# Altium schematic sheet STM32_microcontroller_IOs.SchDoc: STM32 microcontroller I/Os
size A4; Date: Not used; ApprovedBy: Not used; CheckedBy: Not used; Author: Not used; CompanyName: STMicroelectronics; DrawnBy: Not used; Engineer: Not used; Organization: Not used; Address1: Not used; Address2: Not used; Address3: Not used; Address4: Not used; DocumentNumber: 3; Revision: Not used; SheetNumber: 3; SheetTotal: 8
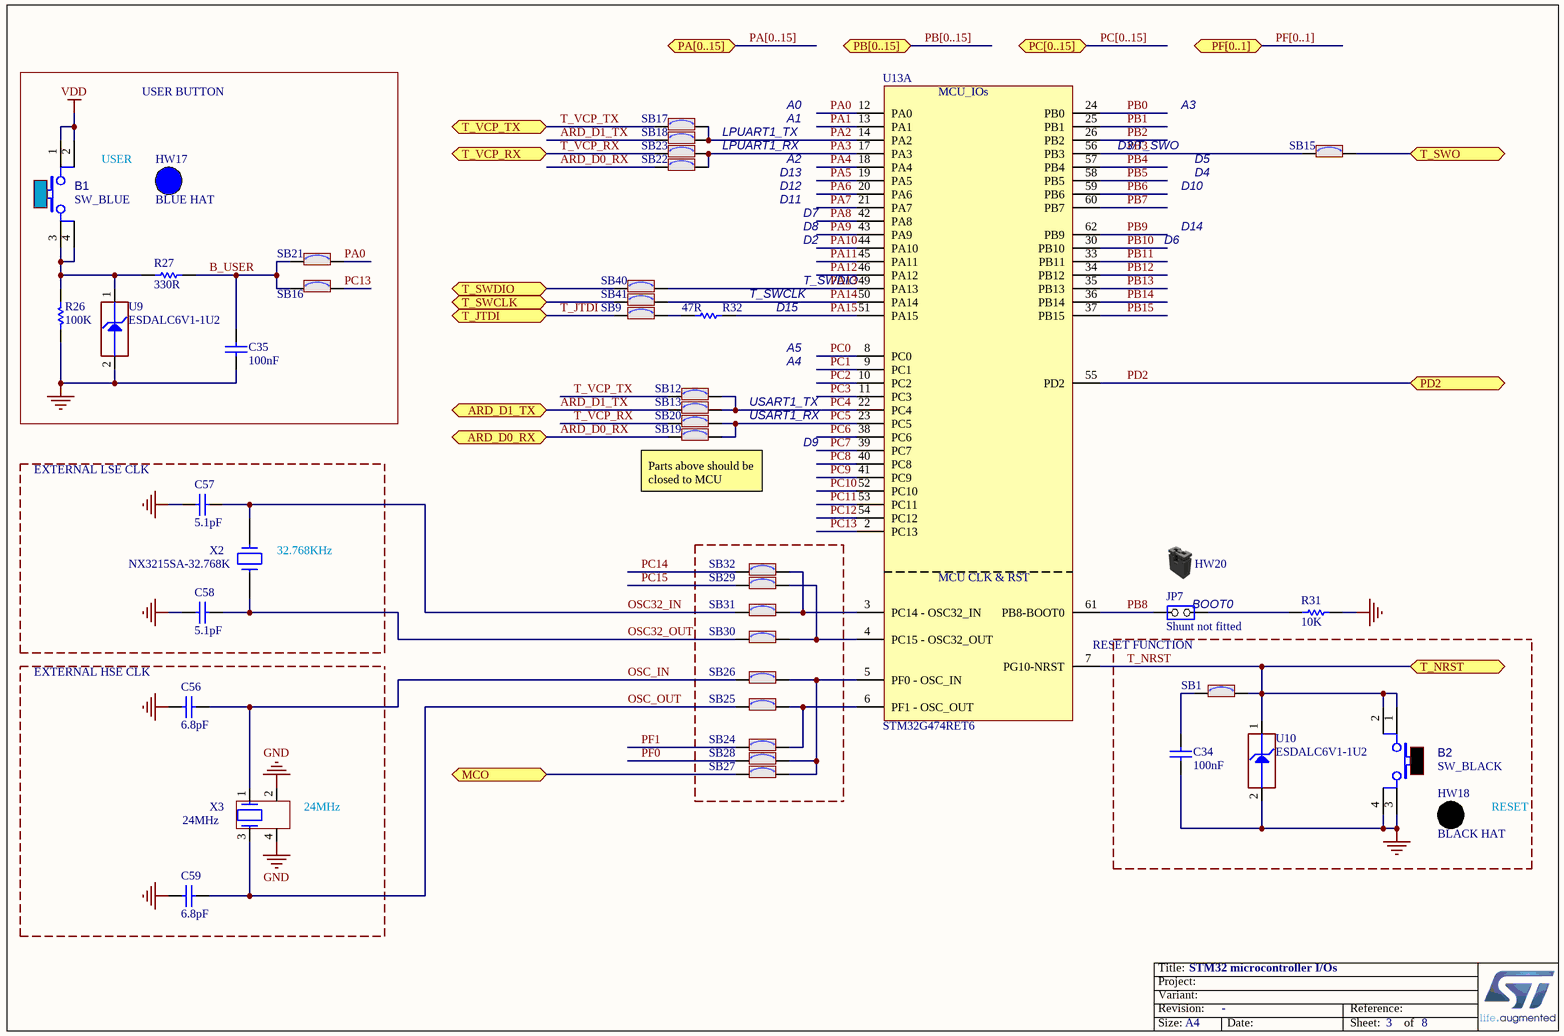
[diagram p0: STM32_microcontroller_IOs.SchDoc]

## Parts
B1  value SW_BLUE  [SWI_WEALTHMETAL_TD-0341_4P_BLUE]
B2  value SW_BLACK  [SWI_WEALTHMETAL_TD-0341_4P_BLACK]
C34  value 100nF  [C0402]
C35  value 100nF  [C0402]
C56  value 6.8pF  [C0402]
C57  value 5.1pF  [C0402]
C58  value 5.1pF  [C0402]
C59  value 6.8pF  [C0402]
HW17  value BLUE HAT  (mechanical)
HW18  value BLACK HAT  (mechanical)
HW20  (no value)  (mechanical)
JP7  value Shunt not fitted  [CON_SAMTEC_TSW-102-07-G-S]
R26  value 100K  [R0603]
R27  value 330R  [R0603]
R31  value 10K  [R0603]
R32  value 47R  [R0402]  (hidden comment: Resistor)
SB1  (no value)  [SOLDER-BRIDGE_R0603-0R]
SB9  (no value)  [SOLDER-BRIDGE_R0603-0R]
SB12  (no value)  [SOLDER-BRIDGE_R0603-0R]
SB13  (no value)  [SOLDER-BRIDGE_R0603-0R]
SB15  (no value)  [SOLDER-BRIDGE_R0603-0R]
SB16  (no value)  [SOLDER-BRIDGE_R0603-0R]
SB17  (no value)  [SOLDER-BRIDGE_R0603-0R]
SB18  (no value)  [SOLDER-BRIDGE_R0603-0R]
SB19  (no value)  [SOLDER-BRIDGE_R0603-0R]
SB20  (no value)  [SOLDER-BRIDGE_R0603-0R]
SB21  (no value)  [SOLDER-BRIDGE_R0603-0R]
SB22  (no value)  [SOLDER-BRIDGE_R0603-0R]
SB23  (no value)  [SOLDER-BRIDGE_R0603-0R]
SB24  (no value)  [SOLDER-BRIDGE_R0603-0R]
SB25  (no value)  [SOLDER-BRIDGE_R0603-0R]
SB26  (no value)  [SOLDER-BRIDGE_R0603-0R]
SB27  (no value)  [SOLDER-BRIDGE_R0603-0R]
SB28  (no value)  [SOLDER-BRIDGE_R0603-0R]
SB29  (no value)  [SOLDER-BRIDGE_R0603-0R]
SB30  (no value)  [SOLDER-BRIDGE_R0603-0R]
SB31  (no value)  [SOLDER-BRIDGE_R0603-0R]
SB32  (no value)  [SOLDER-BRIDGE_R0603-0R]
SB40  (no value)  [SOLDER-BRIDGE_R0603-0R]
SB41  (no value)  [SOLDER-BRIDGE_R0603-0R]
U9  value ESDALC6V1-1U2  [ESD_ST0201]
U10  value ESDALC6V1-1U2  [ESD_ST0201]
U13  value STM32G474RET6  [ICC_LQFP64_10X10_P050_SOCKET_YAMAICHI_IC149-064-069-B5_NM]  (hidden comment: STM32G4xx_LQFP64)  (part A of 2)
X2  value NX3215SA-32.768K  [CRY_NX3215SA_2P]
X3  value 24MHz  [CRY_NX2016SA_4P]

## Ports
ARD_D0_RX, ARD_D1_TX, MCO, PA[0..15] (bidir), PB[0..15] (bidir), PC[0..15] (bidir), PD2, PF[0..1] (bidir), T_JTDI, T_NRST, T_SWCLK, T_SWDIO, T_SWO, T_VCP_RX, T_VCP_TX

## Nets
GND: B2.3 B2.4 C34.1 C35.1 C56.1 C57.2 C58.2 C59.1 R26.1 R31.1 U9.2(GND) U10.2(GND) X3.2 X3.4
VDD: B1.1 B1.2
ARD_D0_RX: SB19.2 SB22.2 ; port ARD_D0_RX
ARD_D1_TX: SB13.2 SB18.2 ; port ARD_D1_TX
B_USER: C35.2 R27.2 SB16.1 SB21.1
MCO: SB27.1 ; port MCO
OSC32_IN: C57.1 SB31.1 X2.1
OSC32_OUT: C58.1 SB30.1 X2.2
OSC_IN: C56.2 SB26.1 X3.1
OSC_OUT: C59.2 SB25.1 X3.3
PA0: SB21.2 U13.12(PA0)
PA1: U13.13(PA1)
PA2: SB17.2 SB18.1 U13.14(PA2)
PA3: SB22.1 SB23.2 U13.17(PA3)
PA4: U13.18(PA4)
PA5: U13.19(PA5)
PA6: U13.20(PA6)
PA7: U13.21(PA7)
PA8: U13.42(PA8)
PA9: U13.43(PA9)
PA10: U13.44(PA10)
PA11: U13.45(PA11)
PA12: U13.46(PA12)
PA13: SB40.2 U13.49(PA13)
PA14: SB41.2 U13.50(PA14)
PA15: R32.2 U13.51(PA15)
PB0: U13.24(PB0)
PB1: U13.25(PB1)
PB2: U13.26(PB2)
PB3: SB15.1 U13.56(PB3)
PB4: U13.57(PB4)
PB5: U13.58(PB5)
PB6: U13.59(PB6)
PB7: U13.60(PB7)
PB8: JP7.1(COMMON) U13.61(PB8-BOOT0)
PB9: U13.62(PB9)
PB10: U13.30(PB10)
PB11: U13.33(PB11)
PB12: U13.34(PB12)
PB13: U13.35(PB13)
PB14: U13.36(PB14)
PB15: U13.37(PB15)
PC0: U13.8(PC0)
PC1: U13.9(PC1)
PC2: U13.10(PC2)
PC3: U13.11(PC3)
PC4: SB12.2 SB13.1 U13.22(PC4)
PC5: SB19.1 SB20.2 U13.23(PC5)
PC6: U13.38(PC6)
PC7: U13.39(PC7)
PC8: U13.40(PC8)
PC9: U13.41(PC9)
PC10: U13.52(PC10)
PC11: U13.53(PC11)
PC12: U13.54(PC12)
PC13: SB16.2 U13.2(PC13)
PC14: SB32.1
PC15: SB29.1
PD2: U13.55(PD2) ; port PD2
PF0: SB28.1
PF1: SB24.1
T_JTDI: SB9.1 ; port T_JTDI
T_NRST: B2.1 B2.2 SB1.2 U10.1(IO1) U13.7(PG10-NRST) ; port T_NRST
T_SWCLK: SB41.1 ; port T_SWCLK
T_SWDIO: SB40.1 ; port T_SWDIO
T_SWO: SB15.2 ; port T_SWO
T_VCP_RX: SB20.1 SB23.1 ; port T_VCP_RX
T_VCP_TX: SB12.1 SB17.1 ; port T_VCP_TX
NetB1_3: B1.3 B1.4 R26.2 R27.1 U9.1(IO1)
NetC34_2: C34.2 SB1.1
NetJP7_2: JP7.2(NO) R31.2
NetR32_1: R32.1 SB9.2
NetSB24_2: SB24.2 SB25.2 U13.6(PF1_-_OSC_OUT)
NetSB26_2: SB26.2 SB27.2 SB28.2 U13.5(PF0_-_OSC_IN)
NetSB29_2: SB29.2 SB30.2 U13.4(PC15_-_OSC32_OUT)
NetSB31_2: SB31.2 SB32.2 U13.3(PC14_-_OSC32_IN)

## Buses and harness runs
bus PA[0..15] = port PA[0..15]
bus PB[0..15] = port PB[0..15]
bus PC[0..15] = port PC[0..15]
bus PF[0..1] = port PF[0..1]

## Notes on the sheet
- USER BUTTON
- A0
- A3
- USER
- LPUART1_TX
- LPUART1_RX
- A1
- A2
- D13
- D3/T_SWO
- D4
- D5
- D12
- D11
- D2
- D7
- D8
- D14
- D10
- D6
- (near R32) T_SWCLK
- D15
- (near R32) T_SWDIO
- A4
- A5
- USART1_RX
- USART1_TX
- D9
- EXTERNAL LSE CLK
- (near SB19) Parts above should be closed to MCU
- (near X2) 32.768KHz
- RESET FUNCTION
- BOOT0
- EXTERNAL HSE CLK
- (near X3) 24MHz
- RESET

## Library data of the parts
B1 = MCD-00002: Non-Open Push-Button 0.1A 24V; Manufacturer_Part_Number: TD0341X-G01-BLU; Manufacturer: WEALTHMETAL; Part_Type: Misc; Provided_By: Subcon; Initial_Board_Reference: MB1274
B2 = MCD-00001: Non-Open Push-Button 0.1A 24V; Manufacturer_Part_Number: TD0341X-G01-BLA; Manufacturer: WEALTHMETAL; Part_Type: Misc; Provided_By: Subcon; Initial_Board_Reference: MB1274
C34 C35 = MCD-00102: Capacitor, MLCC, 100nF, 16V, X7R, 10%, 0402, T=0,5mm; Manufacturer_Part_Number: CC0402KRX7R7BB104; Manufacturer: YAGEO; Provided_By: Subcon; Initial_Board_Reference: MB1262
C56 C59 = MCD-00674: Capacitor, MLCC, 6.8pF, 50V, NPO, +-0.25pF, 0402, T=0.5mm; Manufacturer_Part_Number: CC0402CRNPO9BN6R8; Manufacturer: YAGEO; Provided_By: Subcon; Initial_Board_Reference: MB1319
C57 C58 = MCD-00003: Capacitor, MLCC, 5.1pF, 50V, NPO, +-0.25pF, 0402, T=0.5mm; Manufacturer_Part_Number: CC0402CRNPO9BN5R1; Manufacturer: YAGEO; Provided_By: Subcon; Initial_Board_Reference: MB1274
HW17 = MCD-00634: Blue Hat for switch TD0341X-G01-BLU; Part_Type: Mechanical; Manufacturer_Part_Number: 988.16.09.3.00002_SH-517; Manufacturer: JIUBABA; Provided_By: Subcon; Initial_Board_Reference: MB1319
HW18 = MCD-00635: Black Hat for switch TD0341X-G01-BLA; Part_Type: Mechanical; Manufacturer_Part_Number: 988.16.09.3.00003_SH-517; Manufacturer: JIUBABA; Provided_By: Subcon; Initial_Board_Reference: MB1319
HW20 = MCD-00043: SHUNT 2.54mm BLACK; Manufacturer_Part_Number: SNT-100-BK-G; Manufacturer: SAMTEC; Part_Type: Mechanical; Provided_By: Subcon; Initial_Board_Reference: MB1274
JP7 = MCD-00045: Header, 2x1, 2,54mm, VR, TH, Height 5.84mm/2.54mm; Part_Type: Connector; Manufacturer_Part_Number: TSW-102-07-x-S; Manufacturer: SAMTEC; Provided_By: Subcon; Initial_Board_Reference: MB1274
R26 = MCD-00223: Resistor,100K,0603,1%,1/10W; Manufacturer_Part_Number: RC0603FR-07100KL; Manufacturer: YAGEO; Provided_By: Subcon; Initial_Board_Reference: MB1319
R27 = MCD-00197: Resistor,330R,0603,1%,1/10W; Manufacturer_Part_Number: RC0603FR-07330RL; Manufacturer: YAGEO; Provided_By: Subcon
R31 = MCD-00220: Resistor,10K,0603,1%,1/10W; Manufacturer_Part_Number: RC0603FR-0710KL; Manufacturer: YAGEO; Provided_By: Subcon; Initial_Board_Reference: MB1319
R32 = MCD-00481: Resistor,47R,0402,1%,1/16W; Manufacturer_Part_Number: RC0402FR-0747RL; Manufacturer: YAGEO; Provided_By: SUBCO
SB1 SB9 SB12 SB13 SB15-SB32 SB40 SB41 = MCD-00071: Solder Bridge ON; Part_Type: Mechanical; Provided_By: Subcon; Initial_Board_Reference: MB1274
U9 U10 = MCD-00170: ESD protection 6V1; Part_Type: Diode; Manufacturer: STMICROELECTRONICS; ECCN_US: EAR99; ECCN_EU: NEC; Provided_By: Subcon; Initial_Board_Reference: MB1274
U13 = MCD-01243: STM32G474, LQFP64 package,  3D IC footprint with 2D socket footprint.; Manufacturer: STMICROELECTRONICS; Provided_By: SUBCO with ST control; Initial_Board_Reference: MB1367; Item Type: Item; Path: ws/MCD_ApplicationBoards/Lists/MCDPARTSdatabase
X2 = MCD-00091: Crystal 32.768kHz, 6pF, -+20PPM, R=50K, SMD; Manufacturer_Part_Number: NX3215SA 32.768KHz EXS00A-MU00525; Manufacturer: NDK; Part_Type: Crystal_Osc; ECCN_US: EAR99; ECCN_EU: NEC; Provided_By: STM; Initial_Board_Reference: MB1274
X3 = MCD-01036: 24MHz crystal oscillator - Cl:6pf -; Part_Type: Crystal_Osc; Manufacturer_Part_Number: NX2016SA 24MHz EXS00A-CS10820; Manufacturer: NDK; ECCN_US: EAR99; ECCN_EU: NEC; Provided_By: Subcon; Initial_Board_Reference: MB1332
